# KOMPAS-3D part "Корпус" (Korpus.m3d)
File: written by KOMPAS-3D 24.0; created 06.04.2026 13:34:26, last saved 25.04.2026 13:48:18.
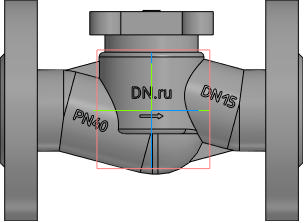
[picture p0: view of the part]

Document properties: Автор: R2D2; Полное имя файла: C:\Работа\ГОТОВЫЕ ИСХОДНИКИ\VSO2130M-F-S Клапан запорный сильфонный DN.ru Ду15-100 Ру40\исходные материалы\DN15\Korpus.m3d

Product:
- Body: Труба / Нестандартная труба / L = 70.4 мм  | qty 1  | 2 such rows
    Материал: Нестандартная труба (density 7856 kg/m3)
    Масса: 2.685704
    Раздел спецификации: Детали
    Примечание: 0,53 кг
    additional columns: Pipeline; 0.035; 0; 0; 0.002; 0.07035; true; 0.04
- Body: Тело 4  | qty 1
    Материал: Нестандартная труба (density 7856 kg/m3)
    Масса: 2.685704
- Body: Тело 5  | qty 1
    Материал: Нестандартная труба (density 7856 kg/m3)
    Масса: 2.685704
- Body: Тело 8  | qty 1
    Материал: Нестандартная труба (density 7856 kg/m3)
    Масса: 2.685704
- Body: Тело 10  | qty 1
    Материал: Нестандартная труба (density 7856 kg/m3)
    Масса: 2.685704
- Body: Тело 11  | qty 1
    Материал: Нестандартная труба (density 7856 kg/m3)
    Масса: 2.685704
- Body: Тело 12  | qty 1
    Материал: Нестандартная труба (density 7856 kg/m3)
    Масса: 2.685704
- Body: Тело 13  | qty 1
    Материал: Нестандартная труба (density 7856 kg/m3)
    Масса: 2.685704
- Part/product: Корпус
    Масса: 6.9

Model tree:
1. Труба:1  (labels: {F703FF30-5BE6-4673-A7F1-8EDA1BE1E2D1}; SHAPEOBJECT3D_ATTR_BUTT; SHAPEOBJECT3D_ATTR_VALID; SHAPEOBJECT3D_ATTR_BUTT_AREA)
     PIPE_R = 3
2. Труба:2  (labels: {F703FF30-5BE6-4673-A7F1-8EDA1BE1E2D1}; SHAPEOBJECT3D_ATTR_BUTT; SHAPEOBJECT3D_ATTR_VALID; SHAPEOBJECT3D_ATTR_BUTT_AREA)
     PIPE_R = 3
3. Колонна
4. Элемент выдавливания:1
     Смещение 1 = -1; Смещение 2 = -5
5. Скругление:17  (with: Ребро.Элемент выдавливания:1)
     Радиус = 2
6. Скругление:18  (with: Ребро.Элемент выдавливания:1)
7. Скругление:24
     Радиус = 1.5
8. Элемент выдавливания:2
     Расстояние 1 = 6
9. Эскиз:4  (with: Грань.Элемент выдавливания:1)
10. Элемент выдавливания:3
     Расстояние 1 = 7.5
11. ОТЛИВКА
12. Скругление:6  (with: Грань.Элемент выдавливания:1)
     Радиус = 2
13. Элемент выдавливания:6  (with: Грань.Элемент выдавливания:1)
     Смещение 1 = 4
14. ЛЕЙБЛ
15. Элемент выдавливания:7  (with: Грань.Элемент выдавливания:1)
     Расстояние 1 = 23.479; Смещение 1 = 1
16. Dn
17. Pn
18. Стрелочка
19. Элемент выдавливания:10  (with: Грань.Труба:1)
     Расстояние 1 = 18.1253; Смещение 1 = 1
20. Элемент выдавливания:11  (with: Грань.Труба:2)
     Расстояние 1 = 18.4585; Смещение 1 = 1
21. Элемент выдавливания:12  (with: Грань.Элемент выдавливания:1)
     Расстояние 1 = 23.4999; Смещение 1 = 1
22. Материал
23. Элемент выдавливания:13  (with: Грань.Элемент выдавливания:1)
     Расстояние 1 = 22.9941; Смещение 1 = 0.5
24. Фланец верх  (with: Грань.Элемент выдавливания:3)
25. Элемент выдавливания:14
     Расстояние 1 = 10
26. Эскиз:18  (with: Грань.Элемент выдавливания:14)
27. Элемент выдавливания:15
     Расстояние 1 = 0.5
28. Эскиз:19  (with: Грань.Элемент выдавливания:14, Ребро.Элемент выдавливания:14)
29. Элемент выдавливания:16  (with: Грань.Элемент выдавливания:14)
     Расстояние 1 = 0.5; Расстояние 2 = 11; Смещение 2 = 1
30. Массив по сетке:1  (with: Элемент выдавливания:16, Эскиз:19)  (4 pattern instances)
     Угол раствора = 90
31. Фланец
32. Элемент вращения:1
     Угол 1 = 360
33. отвертие во фланце  (with: Грань.Элемент вращения:1)
34. Элемент выдавливания:8
35. Массив по концентрической сетке:2  (with: Элемент выдавливания:8, Эскиз:10, Грань.Элемент вращения:1)  (4 pattern instances)
     Шаг 2 = 360
36. Зеркальный массив:1
37. Экземпляр ( 1 )
38. Экземпляр ( 2 )  (with: Элемент вращения:1, Массив по концентрической сетке:2, Экземпляр ( 1 ), Элемент выдавливания:8)
39. Экземпляр ( 3 )  (with: Элемент выдавливания:8)
40. Экземпляр ( 4 )  (with: Элемент выдавливания:8)

Expressions: DS/2+3; DN/2; LL/2; D2/2-3; D2-3*2; D1/2
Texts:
  GOST 26.020 Pr3
  var3D
  GS-C25
  смещение колонны вниз
  LL-10
  DN+20
  DS+5
  Труба / Нестандартная труба / L = %s мм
